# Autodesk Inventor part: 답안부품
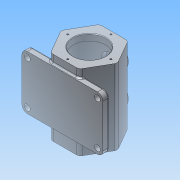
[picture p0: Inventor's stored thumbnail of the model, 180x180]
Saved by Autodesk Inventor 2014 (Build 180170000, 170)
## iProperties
Created: 2021-06
Part Number: 답안부품
Material: 알루미늄 6061
Document SubType Name: Modeling
Designer: net
Density: 2.71 g/cm^3
Appearance: 알루미늄 - 평지
Mass: 1497.73 g
Surface Area: 1110.12 cm^2
Volume: 552.668 cm^3
Author: net
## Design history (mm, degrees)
sketch "스케치1" dims "d0" = 105
  geometry: L1 (52.5, 0)-(26.25, -45.466); L2 (26.25, -45.466)-(-26.25, -45.466); L3 (-26.25, -45.466)-(-52.5, 0); L4 (-52.5, 0)-(-26.25, 45.466); L5 (-26.25, 45.466)-(26.25, 45.466); L6 (26.25, 45.466)-(52.5, 0); 4 further points
  constraints: 12 end point, 2 coincident, 1 horizontal alignment, 1 midpoint, 1 vertical alignment, 15 other
  dimensions: "d1" = 52.5 distance of L4.end L5.end (derived)
extrude "돌출1" new body sketch "스케치1" stored distance "d2" = 140; taper "d3" = 0 deg
sketch "스케치3"
  geometry: L1 (45.466, -70)-(-45.466, -70) reference; L2 (-45.466, -70)-(-45.466, 70) reference; L3 (-45.466, 70)-(45.466, 70) reference; L4 (45.466, 70)-(45.466, -70) reference; L5 (45.466, -70)-(-45.466, -70) reference; L6 (-45.466, -70)-(-45.466, 70) reference; L7 (-45.466, 70)-(45.466, 70) reference; L8 (45.466, 70)-(45.466, -70) reference; L9 (45.466, -70)-(-45.466, -70) reference; L10 (-45.466, -70)-(-45.466, 70) reference; L11 (-45.466, 70)-(45.466, 70) reference; L12 (45.466, 70)-(45.466, -70) reference; L13 (45.466, 70)-(0, 70) reference; L14 (45.466, 70)-(45.466, -70) reference; L15 (0, -70)-(45.466, -70) reference; L16 (-45.466, -70)-(0, -70) reference; L17 (-45.466, 70)-(-45.466, -70) reference; L18 (0, 70)-(-45.466, 70) reference; L19 (45.466, -70)-(-45.466, -70) reference; L20 (-45.466, -70)-(-45.466, 70) reference; L21 (-45.466, 70)-(45.466, 70) reference; L22 (45.466, 70)-(45.466, -70) reference; L23 (0, -70)-(0, 70); L24 (30, -70)-(30, -58); L25 (30, -58)-(37.5, -58); L26 (37.5, -58)-(37.5, 58); L27 (37.5, 58)-(30, 58); L28 (30, 58)-(30, 70); 1 further point
  constraints: 12 end point, 3 parallel, 3 perpendicular, 2 point on line
  dimensions: "d4" = 60 diameter of L24 L23; "d5" = 12 distance of L24.start L24.end; "d6" = 12 distance of L27.end L28.end; "d7" = 60 diameter of L28 L23; "d8" = 75 diameter of L26 L23
revolve "회전1" sketch "스케치3" stored, may be unused: angle "d9" = 90 deg
node "작업 평면1"
sketch "스케치5"
  geometry: L1 (52.5, 0)-(0, 0) reference; L2 (0, 140)-(52.5, 140) reference; L3 (26.25, 140)-(26.25, 0); L4 (78.75, 0)-(52.5, 0) reference; C1 r 20 at (26.25, 100); C2 r 20 at (26.25, 40); 1 further point
  constraints: 2 centre point, 2 end point, 2 midpoint, 2 point on line
  dimensions: "d18" = 40 diameter of C1; "d19" = 40 distance from line of L2 C1.centre; "d20" = 60 distance of C2.centre C1.centre; "d21" = 40 diameter of C2
extrude "돌출3" join sketch "스케치5" distance "d22" = 7; taper "d23" = 0 deg
sketch "스케치6"
  geometry: C1 r 20 at (0, 0) reference; C2 r 20 at (0, -60) reference; C3 r 15 at (0, 0); C4 r 15 at (0, -60); 1 further point
  constraints: 2 centre point, 2 coincident
  dimensions: "d24" = 30 diameter of C3; "d25" = 30 diameter of C4
extrude "돌출4" cut sketch "스케치6" distance "d26" = 8; taper "d27" = 0 deg
sketch "스케치7"
  geometry: C1 r 15 at (0, 0) reference; C2 r 15 at (0, -60) reference; C3 r 12.5 at (0, 0); C4 r 12.5 at (0, -60); 1 further point
  constraints: 2 centre point, 2 coincident
  dimensions: "d28" = 25 diameter of C3; "d29" = 25 diameter of C4
extrude "돌출5" cut sketch "스케치7" stored distance "d30" = 8; taper "d31" = 0 deg
fillet "모깎기2" dims "d39" = 8
fillet "모깎기4" dims "d41" = 5
fillet "모깎기5" dims "d42" = 3
chamfer "모따기1" distance "d43" = 1; stored, may be unused: second distance "d44" = 2, angle "d45" = 45 deg
node "작업 평면2"
sketch "스케치12"
  geometry: L1 (-28.559, -70)-(-50.191, -70) reference; L2 (21.631, -70)-(-21.631, -70) reference; L3 (50.191, -70)-(28.559, -70) reference; L4 (-75, -45)-(75, -45); L5 (75, -45)-(75, 55); L6 (75, 55)-(-75, 55); L7 (-75, 55)-(-75, -45); L8 (-50.191, 70)-(-28.559, 70) reference; L9 (-21.631, 70)-(21.631, 70) reference; L10 (28.559, 70)-(50.191, 70) reference; 2 further points
  constraints: 8 end point, 2 parallel, 1 horizontal, 1 midpoint, 1 perpendicular, 1 vertical alignment
  dimensions: "d62" = 25 distance between parallel lines of L4 L1; "d63" = 15 distance between parallel lines of L8 L6; "d64" = 150 distance between parallel lines of L5 L7
extrude "돌출7" join sketch "스케치12" distance "d65" = 12; taper "d66" = 0 deg
fillet "모깎기6" dims "d67" = 10
sketch "스케치13"
  geometry: L1 (-75, 35)-(-75, -45) reference; L2 (-65, -55)-(-30.561, -55) reference; L3 (-30.561, 45)-(-30.561, -55) reference; L4 (-30.561, 45)-(-65, 45) reference; C1 r 5.5 at (-65, 35); C2 r 5.5 at (-65, -45); C3 r 5.5 at (65, 35); C4 r 5.5 at (65, -45); A1 r 10 centre (65, 35) between (75, 35) and (65, 45) reference; A2 r 10 centre (65, -45) between (65, -55) and (75, -45) reference; A3 r 10 centre (-65, 35) between (-65, 45) and (-75, 35) reference; A4 r 10 centre (-65, -45) between (-75, -45) and (-65, -55) reference; 1 further point
  constraints: 4 centre point, 4 coincident
  dimensions: "d68" = 11 diameter of C1; "d69" = 11 diameter of C2; "d70" = 11 diameter of C4; "d71" = 11 diameter of C3
extrude "돌출8" cut sketch "스케치13" distance "d72" = 12; taper "d73" = 0 deg
fillet "모깎기7" dims "d74" = 3
sketch "스케치14"
  geometry: L1 (72, 35)-(72, -45) reference; L2 (65, 45)-(32.293, 45) reference; 2 further points
  constraints: 1 other
  dimensions: "d75" = 14 distance from line of L1 point (58, -5); "d76" = 50 distance from line of L2 point (58, -5)
feature "엠보싱1" sketch "스케치14" dims "d77" = 0.5, "d78" = 0
sketch "스케치15" dims "d79" = 80
  geometry: C1 r 30 at (0, 0) reference; 2 further points
  constraints: 2 vertical alignment, 1 coincident, 2 other
hole "구멍2" sketch "스케치15" at (0, 40) diameter "d80" = 3.242; stored, may be unused: countersink angle "d84" = 90 deg, drill point angle "d86" = 118 deg; dims "d81" = 8, "d82" = 4, "d83" = 2, "d85" = 10
sketch "스케치16" dims "d90" = 80
  geometry: L1 (21.631, 45.466)-(-21.631, 45.466) reference; L2 (0, 0)-(0, 95.284); L3 (0, 0)-(-64.838, 64.838); C1 r 30 at (0, 0) reference; 2 further points
  constraints: 4 end point, 1 coincident, 1 perpendicular, 1 point on line, 3 other
  dimensions: "d91" = 45 deg angle of L2 L3
hole "구멍3" sketch "스케치16" at (-28.284, 28.284) diameter "d92" = 3.242; stored, may be unused: countersink angle "d96" = 90 deg, drill point angle "d98" = 118 deg; dims "d93" = 8, "d94" = 4, "d95" = 2, "d97" = 10
chamfer "모따기2" distance "d102" = 1; stored, may be unused: second distance "d103" = 2, angle "d104" = 45 deg
node "솔리드1"
pattern_circular "원형 패턴2" dims angle "d88" = 360 deg
pattern_circular "원형 패턴3" dims angle "d100" = 360 deg
node "투영된 루프1"
node "투영된 루프4"
node "절단 모서리 투영2"
node "절단 모서리 투영3"
node "절단 모서리 투영4"
node "절단 모서리 투영5"
